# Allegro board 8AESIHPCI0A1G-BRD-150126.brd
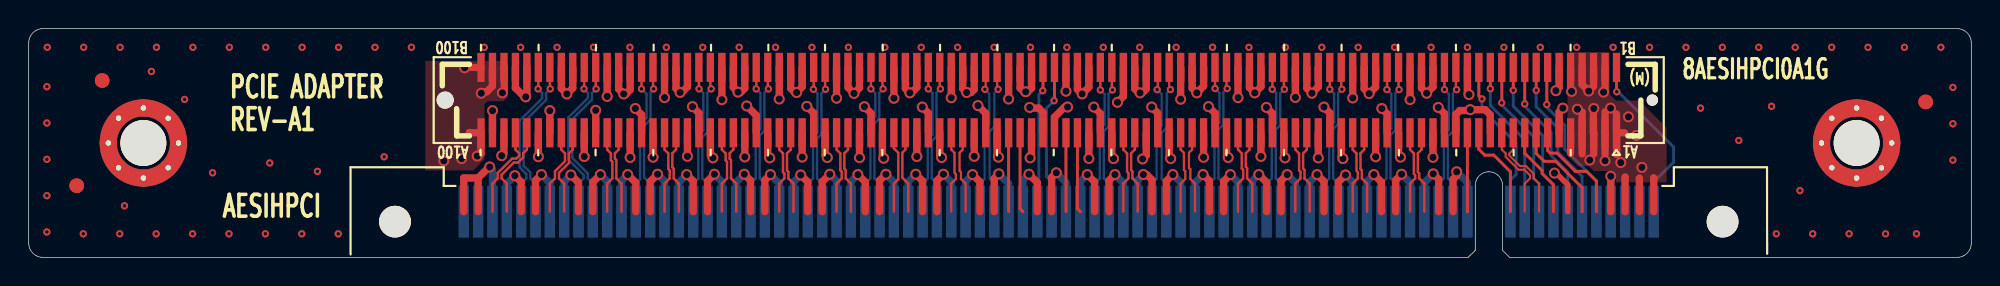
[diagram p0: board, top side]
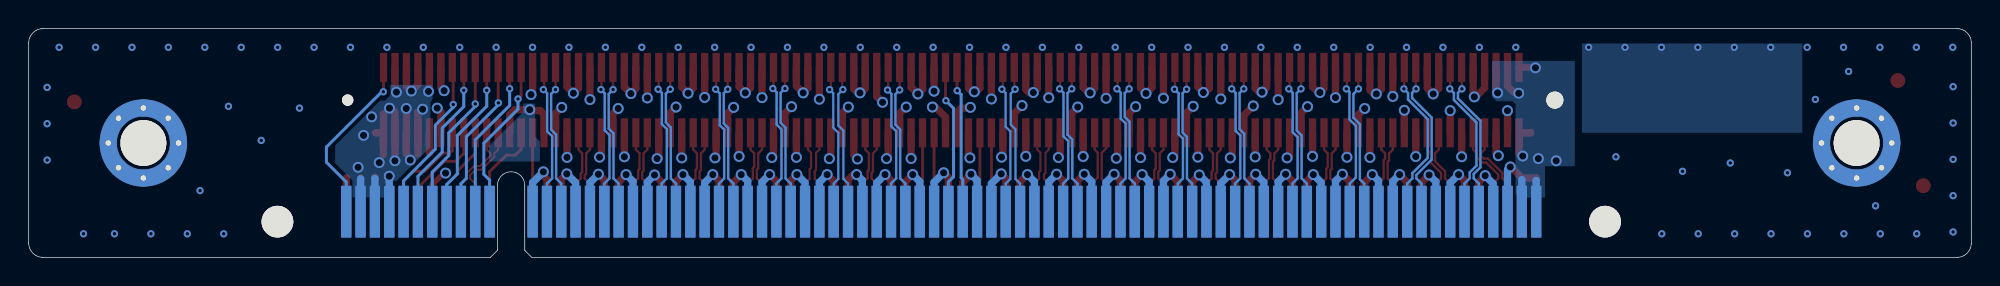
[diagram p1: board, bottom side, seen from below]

Outline 135.5 x 16 mm; copper layers: TOP, L2_GND, L3_GND, BOTTOM. Coordinates in mm from the lower left corner of the outline.

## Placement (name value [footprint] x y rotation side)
A1  3.5mm_8via  [A126_FG]  8 8 0 top
A2  3.5mm_8via  [A126_FG]  127.5 8 0 top
B1  Optics  [2B]  5.13 12.37 0 top
B2  Optics  [2B]  132.32 10.87 0 top
B3  Optics  [2B]  3.35 5.01 0 top
NOREF  -  []  13.9 11.11 0 top
NOREF#2  -  []  11.94 14.05 180 top
NOREF#3  -  []  140.41 20.29 0 top
NOREF#4  -  []  115.22 12.44 0 top
NOREF#5  ***  []  132.08 5.94 270 top
NOREF#6  -  []  0 0 0 top
P1  61083-202402LF  [C_5179029_0]  71.15 11 180 top
P2  2EG28217-D5D6-JF  [PCISR_E_X16_A]  118.15 2.5 180 bottom

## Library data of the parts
A1 A2 = SCREW HOLE_6: Tolerance: ***; User Part Number: ***; room: SCREW
B1-B3 = Optics_solder: Tolerance: ***; User Part Number: ***
P1 = HEADER_2X100B: Tolerance: ***; User Part Number: ***
P2 = 2134415-2_1: Tolerance: ***; User Part Number: ***

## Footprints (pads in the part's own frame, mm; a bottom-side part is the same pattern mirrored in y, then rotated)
2B
  round 1.016 smd: 1(0,0) 2(0,0)
A126_FG
  round 3.2 hole 3.2 unplated: (0,0)
  round 1.194 hole 0.381: 2(1.732,1.732) 3(-1.732,1.732) 4(-1.732,-1.732) 5(1.732,-1.732) 6(0,2.451) 7(0,-2.451) 8(-2.451,0) 9(2.451,0)
C_5179029_0
  round 0.787 hole 0.787 unplated: (-42.1,0)
  round 1.194 hole 1.194 unplated: (42.1,0)
  rect 0.508x2.032 smd: A1(-39.6,2.286) A2(-38.8,2.286) A3(-38,2.286) A4(-37.2,2.286) A5(-36.4,2.286) A6(-35.6,2.286) A7(-34.8,2.286) A8(-34,2.286) A9(-33.2,2.286) A10(-32.4,2.286) A11(-31.6,2.286) A12(-30.8,2.286) A13(-30,2.286) A14(-29.2,2.286) A15(-28.4,2.286) A16(-27.6,2.286) A17(-26.8,2.286) A18(-26,2.286) A19(-25.2,2.286) A20(-24.4,2.286) A21(-23.6,2.286) A22(-22.8,2.286) A23(-22,2.286) A24(-21.2,2.286) A25(-20.4,2.286) A26(-19.6,2.286) A27(-18.8,2.286) A28(-18,2.286) A29(-17.2,2.286) A30(-16.4,2.286) A31(-15.6,2.286) A32(-14.8,2.286) A33(-14,2.286) A34(-13.2,2.286) A35(-12.4,2.286) A36(-11.6,2.286) A37(-10.8,2.286) A38(-10,2.286) A39(-9.2,2.286) A40(-8.4,2.286) A41(-7.6,2.286) A42(-6.8,2.286) A43(-6,2.286) A44(-5.2,2.286) A45(-4.4,2.286) A46(-3.6,2.286) A47(-2.8,2.286) A48(-2,2.286) A49(-1.2,2.286) A50(-0.4,2.286) A51(0.4,2.286) A52(1.2,2.286) A53(2,2.286) A54(2.8,2.286) A55(3.6,2.286) A56(4.4,2.286) A57(5.2,2.286) A58(6,2.286) A59(6.8,2.286) A60(7.6,2.286) A61(8.4,2.286) A62(9.2,2.286) A63(10,2.286) A64(10.8,2.286) A65(11.6,2.286) A66(12.4,2.286) A67(13.2,2.286) A68(14,2.286) A69(14.8,2.286) A70(15.6,2.286) A71(16.4,2.286) A72(17.2,2.286) A73(18,2.286) A74(18.8,2.286) A75(19.6,2.286) A76(20.4,2.286) A77(21.2,2.286) A78(22,2.286) A79(22.8,2.286) A80(23.6,2.286) A81(24.4,2.286) A82(25.2,2.286) A83(26,2.286) A84(26.8,2.286) A85(27.6,2.286) A86(28.4,2.286) A87(29.2,2.286) A88(30,2.286) A89(30.8,2.286) A90(31.6,2.286) A91(32.4,2.286) A92(33.2,2.286) A93(34,2.286) A94(34.8,2.286) A95(35.6,2.286) A96(36.4,2.286) A97(37.2,2.286) A98(38,2.286) A99(38.8,2.286) A100(39.6,2.286) B1(-39.6,-2.286) B2(-38.8,-2.286) B3(-38,-2.286) B4(-37.2,-2.286) B5(-36.4,-2.286) B6(-35.6,-2.286) B7(-34.8,-2.286) B8(-34,-2.286) B9(-33.2,-2.286) B10(-32.4,-2.286) B11(-31.6,-2.286) B12(-30.8,-2.286) B13(-30,-2.286) B14(-29.2,-2.286) B15(-28.4,-2.286) B16(-27.6,-2.286) B17(-26.8,-2.286) B18(-26,-2.286) B19(-25.2,-2.286) B20(-24.4,-2.286) B21(-23.6,-2.286) B22(-22.8,-2.286) B23(-22,-2.286) B24(-21.2,-2.286) B25(-20.4,-2.286) B26(-19.6,-2.286) B27(-18.8,-2.286) B28(-18,-2.286) B29(-17.2,-2.286) B30(-16.4,-2.286) B31(-15.6,-2.286) B32(-14.8,-2.286) B33(-14,-2.286) B34(-13.2,-2.286) B35(-12.4,-2.286) B36(-11.6,-2.286) B37(-10.8,-2.286) B38(-10,-2.286) B39(-9.2,-2.286) B40(-8.4,-2.286) B41(-7.6,-2.286) B42(-6.8,-2.286) B43(-6,-2.286) B44(-5.2,-2.286) B45(-4.4,-2.286) B46(-3.6,-2.286) B47(-2.8,-2.286) B48(-2,-2.286) B49(-1.2,-2.286) B50(-0.4,-2.286) B51(0.4,-2.286) B52(1.2,-2.286) B53(2,-2.286) B54(2.8,-2.286) B55(3.6,-2.286) B56(4.4,-2.286) B57(5.2,-2.286) B58(6,-2.286) B59(6.8,-2.286) B60(7.6,-2.286) B61(8.4,-2.286) B62(9.2,-2.286) B63(10,-2.286) B64(10.8,-2.286) B65(11.6,-2.286) B66(12.4,-2.286) B67(13.2,-2.286) B68(14,-2.286) B69(14.8,-2.286) B70(15.6,-2.286) B71(16.4,-2.286) B72(17.2,-2.286) B73(18,-2.286) B74(18.8,-2.286) B75(19.6,-2.286) B76(20.4,-2.286) B77(21.2,-2.286) B78(22,-2.286) B79(22.8,-2.286) B80(23.6,-2.286) B81(24.4,-2.286) B82(25.2,-2.286) B83(26,-2.286) B84(26.8,-2.286) B85(27.6,-2.286) B86(28.4,-2.286) B87(29.2,-2.286) B88(30,-2.286) B89(30.8,-2.286) B90(31.6,-2.286) B91(32.4,-2.286) B92(33.2,-2.286) B93(34,-2.286) B94(34.8,-2.286) B95(35.6,-2.286) B96(36.4,-2.286) B97(37.2,-2.286) B98(38,-2.286) B99(38.8,-2.286) B100(39.6,-2.286)
PCISR_E_X16_A
  round 2.21 hole 2.21 unplated: (0,0) (92.6,0)
  rect 0.711x3.607 smd: A1(4.8,0.7) A2(5.8,0.7) A3(6.8,0.7) A4(7.8,0.7) A5(8.8,0.7) A6(9.8,0.7) A7(10.8,0.7) A8(11.8,0.7) A9(12.8,0.7) A10(13.8,0.7) A11(14.8,0.7) A12(17.8,0.7) A13(18.8,0.7) A14(19.8,0.7) A15(20.8,0.7) A16(21.8,0.7) A17(22.8,0.7) A18(23.8,0.7) A19(24.8,0.7) A20(25.8,0.7) A21(26.8,0.7) A22(27.8,0.7) A23(28.8,0.7) A24(29.8,0.7) A25(30.8,0.7) A26(31.8,0.7) A27(32.8,0.7) A28(33.8,0.7) A29(34.8,0.7) A30(35.8,0.7) A31(36.8,0.7) A32(37.8,0.7) A33(38.8,0.7) A34(39.8,0.7) A35(40.8,0.7) A36(41.8,0.7) A37(42.8,0.7) A38(43.8,0.7) A39(44.8,0.7) A40(45.8,0.7) A41(46.8,0.7) A42(47.8,0.7) A43(48.8,0.7) A44(49.8,0.7) A45(50.8,0.7) A46(51.8,0.7) A47(52.8,0.7) A48(53.8,0.7) A49(54.8,0.7) A50(55.8,0.7) A51(56.8,0.7) A52(57.8,0.7) A53(58.8,0.7) A54(59.8,0.7) A55(60.8,0.7) A56(61.8,0.7) A57(62.8,0.7) A58(63.8,0.7) A59(64.8,0.7) A60(65.8,0.7) A61(66.8,0.7) A62(67.8,0.7) A63(68.8,0.7) A64(69.8,0.7) A65(70.8,0.7) A66(71.8,0.7) A67(72.8,0.7) A68(73.8,0.7) A69(74.8,0.7) A70(75.8,0.7) A71(76.8,0.7) A72(77.8,0.7) A73(78.8,0.7) A74(79.8,0.7) A75(80.8,0.7) A76(81.8,0.7) A77(82.8,0.7) A78(83.8,0.7) A79(84.8,0.7) A80(85.8,0.7) A81(86.8,0.7) A82(87.8,0.7) B1(4.8,0.7) B2(5.8,0.7) B3(6.8,0.7) B4(7.8,0.7) B5(8.8,0.7) B6(9.8,0.7) B7(10.8,0.7) B8(11.8,0.7) B9(12.8,0.7) B10(13.8,0.7) B11(14.8,0.7) B12(17.8,0.7) B13(18.8,0.7) B14(19.8,0.7) B15(20.8,0.7) B16(21.8,0.7) B17(22.8,0.7) B18(23.8,0.7) B19(24.8,0.7) B20(25.8,0.7) B21(26.8,0.7) B22(27.8,0.7) B23(28.8,0.7) B24(29.8,0.7) B25(30.8,0.7) B26(31.8,0.7) B27(32.8,0.7) B28(33.8,0.7) B29(34.8,0.7) B30(35.8,0.7) B31(36.8,0.7) B32(37.8,0.7) B33(38.8,0.7) B34(39.8,0.7) B35(40.8,0.7) B36(41.8,0.7) B37(42.8,0.7) B38(43.8,0.7) B39(44.8,0.7) B40(45.8,0.7) B41(46.8,0.7) B42(47.8,0.7) B43(48.8,0.7) B44(49.8,0.7) B45(50.8,0.7) B46(51.8,0.7) B47(52.8,0.7) B48(53.8,0.7) B49(54.8,0.7) B50(55.8,0.7) B51(56.8,0.7) B52(57.8,0.7) B53(58.8,0.7) B54(59.8,0.7) B55(60.8,0.7) B56(61.8,0.7) B57(62.8,0.7) B58(63.8,0.7) B59(64.8,0.7) B60(65.8,0.7) B61(66.8,0.7) B62(67.8,0.7) B63(68.8,0.7) B64(69.8,0.7) B65(70.8,0.7) B66(71.8,0.7) B67(72.8,0.7) B68(73.8,0.7) B69(74.8,0.7) B70(75.8,0.7) B71(76.8,0.7) B72(77.8,0.7) B73(78.8,0.7) B74(79.8,0.7) B75(80.8,0.7) B76(81.8,0.7) B77(82.8,0.7) B78(83.8,0.7) B79(84.8,0.7) B80(85.8,0.7) B81(86.8,0.7) B82(87.8,0.7)

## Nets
12V_1: P1.A1(A1_P12V) P1.A2(A2_P12V) P1.A3(A3_P12V) P1.A4(A4_P12V) P1.A5(A5_P12V) P1.B2(B2_P12V) P1.B3(B3_P12V) P1.B4(B4_P12V) P1.B5(B5_P12V) P2.A2(P12V#A2) P2.A3(P12V#A3) P2.B1(P12V#B1) P2.B2(P12V#B2) P2.B3(P12V#B3)
12V_2: P1.A100(A100_P12V) P1.B98(B98_P12V) P1.B99(B99_P12V) P1.B100(B100_P12V) P2.A81(P12V#A81) P2.A82(P12V#A82)
GND: A1.2 A1.3 A1.4 A1.5 A1.6 A1.7 A1.8 A1.9 A2.2 A2.3 A2.4 A2.5 A2.6 A2.7 A2.8 A2.9 P1.A6(A6_GND) P1.A12(A12_USB_N) P1.A15(A15_GND) P1.A16(A16_GND) P1.A17(A17_GND) P1.A20(A20_GND) P1.A21(A21_GND) P1.A22(A22_GND) P1.A25(A25_GND) P1.A26(A26_GND) P1.A27(A27_GND) P1.A30(A30_GND) P1.A31(A31_GND) P1.A32(A32_GND) P1.A35(A35_GND) P1.A36(A36_GND) P1.A37(A37_GND) P1.A40(A40_GND) P1.A41(A41_GND) P1.A42(A42_GND) P1.A45(A45_GND) P1.A46(A46_GND) P1.A47(A47_GND) P1.A50(A50_GND) P1.A51(A51_GND) P1.A52(A52_GND) P1.A55(A55_GND) P1.A56(A56_GND) P1.A57(A57_GND) P1.A60(A60_GND) P1.A61(A61_GND) P1.A62(A62_GND) P1.A65(A65_GND) P1.A66(A66_GND) P1.A67(A67_GND) P1.A70(A70_GND) P1.A71(A71_GND) P1.A72(A72_GND) P1.A75(A75_GND) P1.A76(A76_GND) P1.A77(A77_GND) P1.A80(A80_GND) P1.A81(A81_GND) P1.A82(A82_GND) P1.A85(A85_GND) P1.A86(A86_GND) P1.A87(A87_GND) P1.A90(A90_GND) P1.A91(A91_GND) P1.A94(A94_GND) P1.A95(A95_GND) P1.A98(A98_GND) P1.A99(A99_GND) P1.B6(B6_GND) P1.B14(B14_GND) P1.B17(B17_GND) P1.B18(B18_GND) P1.B19(B19_GND) P1.B22(B22_GND) P1.B23(B23_GND) P1.B24(B24_GND) P1.B27(B27_GND) P1.B28(B28_GND) P1.B29(B29_GND) P1.B32(B32_GND) P1.B33(B33_GND) P1.B34(B34_GND) P1.B37(B37_GND) P1.B38(B38_GND) P1.B39(B39_GND) P1.B42(B42_GND) P1.B43(B43_GND) P1.B44(B44_GND) P1.B47(B47_GND) P1.B48(B48_GND) P1.B49(B49_GND) P1.B52(B52_GND) P1.B53(B53_GND) P1.B54(B54_GND) P1.B57(B57_GND) P1.B58(B58_GND) P1.B59(B59_GND) P1.B62(B62_GND) P1.B63(B63_GND) P1.B64(B64_GND) P1.B67(B67_GND) P1.B68(B68_GND) P1.B69(B69_GND) P1.B72(B72_GND) P1.B73(B73_GND) P1.B74(B74_GND) P1.B77(B77_GND) P1.B78(B78_GND) P1.B79(B79_GND) P1.B82(B82_GND) P1.B83(B83_GND) P1.B84(B84_GND) P1.B87(B87_GND) P1.B88(B88_GND) P1.B89(B89_GND) P1.B92(B92_GND) P1.B93(B93_GND) P1.B96(B96_GND) P1.B97(B97_GND) P2.A4(GND#A4) P2.A12(GND#A12) P2.A15(GND#A15) P2.A16(GND#A16) P2.A19(GND#A19) P2.A20(GND#A20) P2.A23(GND#A23) P2.A24(GND#A24) P2.A27(GND#A27) P2.A28(GND#A28) P2.A31(GND#A31) P2.A32(GND#A32) P2.A35(GND#A35) P2.A36(GND#A36) P2.A39(GND#A39) P2.A40(GND#A40) P2.A43(GND#A43) P2.A44(GND#A44) P2.A47(GND#A47) P2.A48(GND#A48) P2.A51(GND#A51) P2.A52(GND#A52) P2.A55(GND#A55) P2.A56(GND#A56) P2.A59(GND#A59) P2.A60(GND#A60) P2.A63(GND#A63) P2.A64(GND#A64) P2.A67(GND#A67) P2.A68(GND#A68) P2.A71(GND#A71) P2.A72(GND#A72) P2.A75(GND#A75) P2.A76(GND#A76) P2.A79(GND#A79) P2.A80(GND#A80) P2.B4(GND#B4) P2.B7(GND#B7) P2.B13(GND#B13) P2.B14(GND#B14) P2.B17(GND#B17) P2.B18(GND#B18) P2.B21(GND#B21) P2.B22(GND#B22) P2.B25(GND#B25) P2.B26(GND#B26) P2.B29(GND#B29) P2.B30(GND#B30) P2.B33(GND#B33) P2.B34(GND#B34) P2.B37(GND#B37) P2.B38(GND#B38) P2.B41(GND#B41) P2.B42(GND#B42) P2.B45(GND#B45) P2.B46(GND#B46) P2.B49(GND#B49) P2.B50(GND#B50) P2.B53(GND#B53) P2.B54(GND#B54) P2.B57(GND#B57) P2.B58(GND#B58) P2.B61(GND#B61) P2.B62(GND#B62) P2.B65(GND#B65) P2.B66(GND#B66) P2.B69(GND#B69) P2.B70(GND#B70) P2.B73(GND#B73) P2.B74(GND#B74) P2.B77(GND#B77) P2.B78(GND#B78) P2.B81(GND#B81) P2.B82(GND#B82)
COM_RX: P1.B10(B10_COM_RX) P2.A8(COM_RX)
COM_TX: P1.B9(B9_COM_TX) P2.A7(COM_TX)
GE0_RX_N: P1.B56(B56_GE0_RX_N) P2.A46(GE0_RX_N)
GE0_RX_P: P1.B55(B55_GE0_RX_P) P2.A45(GE0_RX_P)
GE0_TX_N: P1.A59(A59_GE0_TX_N) P2.B48(GE0_TX_N)
GE0_TX_P: P1.A58(A58_GE0_TX_P) P2.B47(GE0_TX_P)
I2C_ALERT_N: P1.A14(A14_I2C_ALERT) P2.B12(I2C_ALERT#)
I2C_DATA: P1.A8(A8_I2C_DATA) P2.B6(I2C_DATA)
I2C_SCL: P1.A7(A7_I2C_SCL) P2.B5(I2C_SCL)
NIC_SMBUS_ALERT: P1.B51(B51_NIC_SMBUS_ALERT#) P2.A42(NIC_SMBUS_ALERT#)
NIC_SMBUS_SCL: P1.A53(A53_NIC_SMBUS_SCL) P2.B43(NIC_SMBUS_SCL)
NIC_SMBUS_SDA: P1.A54(A54_NIC_SMBUS_SDA) P2.B44(NIC_SMBUS_SDA)
PCIE0_REFCLK_N: P1.B16(B16_PCIE0_REFCLK_N) P2.A14(PCIE0_REFCLK_N)
PCIE0_REFCLK_P: P1.B15(B15_PCIE0_REFCLK_P) P2.A13(PCIE0_REFCLK_P)
PCIE0_RST_N: P1.B13(B13_PCIE0_RESET#) P2.A11(PCIE0_RESET#)
PCIE0_RX0_N: P1.B21(B21_PCIE0_RX0_N) P2.A18(PCIE0_RX0_N)
PCIE0_RX0_P: P1.B20(B20_PCIE0_RX0_P) P2.A17(PCIE0_RX0_P)
PCIE0_RX1_N: P1.B26(B26_PCIE0_RX1_N) P2.A22(PCIE0_RX1_N)
PCIE0_RX1_P: P1.B25(B25_PCIE0_RX1_P) P2.A21(PCIE0_RX1_P)
PCIE0_RX2_N: P1.B31(B31_PCIE0_RX2_N) P2.A26(PCIE0_RX2_N)
PCIE0_RX2_P: P1.B30(B30_PCIE0_RX2_P) P2.A25(PCIE0_RX2_P)
PCIE0_RX3_N: P1.B36(B36_PCIE0_RX3_N) P2.A30(PCIE0_RX3_N)
PCIE0_RX3_P: P1.B35(B35_PCIE0_RX3_P) P2.A29(PCIE0_RX3_P)
PCIE0_RX4_N: P1.B61(B61_PCIE0_RX4_N) P2.A50(PCIE0_RX4_N)
PCIE0_RX4_P: P1.B60(B60_PCIE0_RX4_P) P2.A49(PCIE0_RX4_P)
PCIE0_RX5_N: P1.B66(B66_PCIE0_RX5_N) P2.A54(PCIE0_RX5_N)
PCIE0_RX5_P: P1.B65(B65_PCIE0_RX5_P) P2.A53(PCIE0_RX5_P)
PCIE0_RX6_N: P1.B71(B71_PCIE0_RX6_N) P2.A58(PCIE0_RX6_N)
PCIE0_RX6_P: P1.B70(B70_PCIE0_RX6_P) P2.A57(PCIE0_RX6_P)
PCIE0_RX7_N: P1.B76(B76_PCIE0_RX7_N) P2.A62(PCIE0_RX7_N)
PCIE0_RX7_P: P1.B75(B75_PCIE0_RX7_P) P2.A61(PCIE0_RX7_P)
PCIE0_TX0_N: P1.A19(A19_PCIE0_TX0_N) P2.B16(PCIE0_TX0_N)
PCIE0_TX0_P: P1.A18(A18_PCIE0_TX0_P) P2.B15(PCIE0_TX0_P)
PCIE0_TX1_N: P1.A24(A24_PCIE0_TX1_N) P2.B20(PCIE0_TX1_N)
PCIE0_TX1_P: P1.A23(A23_PCIE0_TX1_P) P2.B19(PCIE0_TX1_P)
PCIE0_TX2_N: P1.A29(A29_PCIE0_TX2_N) P2.B24(PCIE0_TX2_N)
PCIE0_TX2_P: P1.A28(A28_PCIE0_TX2_P) P2.B23(PCIE0_TX2_P)
PCIE0_TX3_N: P1.A34(A34_PCIE0_TX3_N) P2.B28(PCIE0_TX3_N)
PCIE0_TX3_P: P1.A33(A33_PCIE0_TX3_P) P2.B27(PCIE0_TX3_P)
PCIE0_TX4_N: P1.A64(A64_PCIE0_TX4_N) P2.B52(PCIE0_TX4_N)
PCIE0_TX4_P: P1.A63(A63_PCIE0_TX4_P) P2.B51(PCIE0_TX4_P)
PCIE0_TX5_N: P1.A69(A69_PCIE0_TX5_N) P2.B56(PCIE0_TX5_N)
PCIE0_TX5_P: P1.A68(A68_PCIE0_TX5_P) P2.B55(PCIE0_TX5_P)
PCIE0_TX6_N: P1.A74(A74_PCIE0_TX6_N) P2.B60(PCIE0_TX6_N)
PCIE0_TX6_P: P1.A73(A73_PCIE0_TX6_P) P2.B59(PCIE0_TX6_P)
PCIE0_TX7_N: P1.A79(A79_PCIE0_TX7_N) P2.B64(PCIE0_TX7_N)
PCIE0_TX7_P: P1.A78(A78_PCIE0_TX7_P) P2.B63(PCIE0_TX7_P)
PCIE1_REFCLK_N: P1.A44(A44_PCIE1_REFCLK_N) P2.B36(PCIE1_REFCLK_N)
PCIE1_REFCLK_P: P1.A43(A43_PCIE1_REFCLK_P) P2.B35(PCIE1_REFCLK_P)
PCIE1_RST_N: P1.A48(A48_PCIE1_RESET#) P2.B39(PCIE1_RESET#)
PCIE1_RX0_N: P1.B81(B81_PCIE1_RX0_N) P2.A66(PCIE1_RX0_N)
PCIE1_RX0_P: P1.B80(B80_PCIE1_RX0_P) P2.A65(PCIE1_RX0_P)
PCIE1_RX1_N: P1.B86(B86_PCIE1_RX1_N) P2.A70(PCIE1_RX1_N)
PCIE1_RX1_P: P1.B85(B85_PCIE1_RX1_P) P2.A69(PCIE1_RX1_P)
PCIE1_RX2_N: P1.B91(B91_PCIE1_RX2_N) P2.A74(PCIE1_RX2_N)
PCIE1_RX2_P: P1.B90(B90_PCIE1_RX2_P) P2.A73(PCIE1_RX2_P)
PCIE1_RX3_N: P1.B95(B95_PCIE1_RX3_N) P2.A78(PCIE1_RX3_N)
PCIE1_RX3_P: P1.B94(B94_PCIE1_RX3_P) P2.A77(PCIE1_RX3_P)
PCIE1_TX0_N: P1.A84(A84_PCIE1_TX0_N) P2.B68(PCIE1_TX0_N)
PCIE1_TX0_P: P1.A83(A83_PCIE1_TX0_P) P2.B67(PCIE1_TX0_P)
PCIE1_TX1_N: P1.A89(A89_PCIE1_TX1_N) P2.B72(PCIE1_TX1_N)
PCIE1_TX1_P: P1.A88(A88_PCIE1_TX1_P) P2.B71(PCIE1_TX1_P)
PCIE1_TX2_N: P1.A93(A93_PCIE1_TX2_N) P2.B76(PCIE1_TX2_N)
PCIE1_TX2_P: P1.A92(A92_PCIE1_TX2_P) P2.B75(PCIE1_TX2_P)
PCIE1_TX3_N: P1.A97(A97_PCIE1_TX3_N) P2.B80(PCIE1_TX3_N)
PCIE1_TX3_P: P1.A96(A96_PCIE1_TX3_P) P2.B79(PCIE1_TX3_P)
PCIE2_REFCLK_N: P1.B46(B46_PCIE2_REFCLK_N) P2.A38(PCIE2_REFCLK_N)
PCIE2_REFCLK_P: P1.B45(B45_PCIE2_REFCLK_P) P2.A37(PCIE2_REFCLK_P)
PCIE2_RST_N: P1.A49(A49_PCIE2_RESET#) P2.B40(PCIE2_RESET#)
PRSNT_N: P1.B1(B1_PRSNT#) P2.A1(PRSNT#)
PWR_BTN_N: P1.A9(A9_GND) P2.B8(PWR_BTN#)
RFU: P1.B50(B50_RFU) P2.A41(RFU)
SATA0_RX_N: P1.B41(B41_SATA0_RX_N) P2.A34(SATA0_RX_N)
SATA0_RX_P: P1.B40(B40_SATA0_RX_P) P2.A33(SATA0_RX_P)
SATA0_TX_N: P1.A39(A39_SATA0_TX_N) P2.B32(SATA0_TX_N)
SATA0_TX_P: P1.A38(A38_SATA0_TX_P) P2.B31(SATA0_TX_P)
SVR_ID0: P1.B7(B7_SVR_ID0/GPIO0) P2.A5(SVR_ID0/GPIO0)
SVR_ID1: P1.B8(B8_SVR_ID1/GPIO1) P2.A6(SVR_ID1/GPIO1)
SVR_ID2: P1.B11(B11_SVR_ID2/GPIO2) P2.A9(SVR_ID2/GPIO2)
SVR_ID3: P1.B12(B12_SVR_ID3/GPIO3) P2.A10(SVR_ID3/GPIO3)
SYS_RST_N: P1.A13(A13_SYS_RESET#) P2.B11(SYS_RESET#)
USB_DN: P1.A11(A11_USB_P) P2.B10(USB_N)
USB_DP: P1.A10(A10_PWR_BTN#) P2.B9(USB_P)

Pads without a net: B1 1 2; B2 1 2; B3 1 2

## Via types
v1: diameter 0.762, hole 0.508, TOP to BOTTOM, 141 vias
v2: diameter 0.508, hole 0.254, TOP to BOTTOM, 126 vias

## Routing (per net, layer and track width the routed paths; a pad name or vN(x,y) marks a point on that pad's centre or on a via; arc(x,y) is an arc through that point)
12V_1: length 32.6
  TOP w0.508: P2.A2 112.35,5.53 112.34,5.54 ; 109.95,7.21 109.95,8.71 ; 109.95,8.71 109.95,10.19 ; 109.95,8.71 P1.A2 ; P2.A3 111.35,5.61 111.35,5.61 ; 108.35,7.24 108.35,8.71 P1.A4 108.35,10.16 108.35,10.16 ; P1.B2 109.95,11.66 v1(109.85,11.56) ; 111.31,8.71 110.77,8.71 ; 110.77,8.71 P1.A1 110.75,10.04 ; 110.77,8.71 110.77,7.19 ; 109.16,7.24 109.16,8.71 P1.A3 109.14,8.71 109.14,10.21 ; P1.B4 108.35,12.09 v1(108.81,11.63) 109.15,11.97 P1.B3 ; v1(107.62,11.61) 107.55,11.67 P1.B5 ; P1.A5 107.55,7.28 ; 113.33,5.56 113.35,5.55 P2.B1
  BOTTOM w0.508: P2.A2 112.35,5.48 112.34,5.49 ; 111.35,5.51 111.35,5.51 P2.A3
  vias: v1(108.02,10.36) v1(108.89,6.81) v1(109.16,10.41) v1(109.95,6.76) v1(110.33,10.44) v1(111.05,6.63) v1(111.58,9.83) v1(112.14,8.53) v1(112.52,6.3)
12V_2: length 12.3
  TOP w0.508: v1(30.41,13.26) 30.43,13.29 P1.B100 ; v1(31.29,7.09) 31.39,7.09 31.55,7.25 P1.A100 30.75,8.71 30.73,8.74 ; P1.B98 33.17,13.27 33.17,11.63 v1(33.04,11.51) ; v1(31.57,11.48) 31.67,11.58 31.95,11.58 32.35,11.98 P1.B99
  BOTTOM w0.508: P2.A81 31.35,5.43 31.34,5.44 ; P2.A82 30.35,5.38 30.35,5.38
  vias: v1(28.96,6.76) v1(30.2,6.91)
GND: length 412.2
  TOP w0.381: v1(106.42,5.9) 106.54,5.9 107.35,5.09 P2.B7
  TOP w0.508: 31.35,5.56 32.12,6.32 v1(32.16,6.32) ; 31.35,5.56 P2.B81 ; 31.35,5.56 30.35,5.56 P2.B82 ; P1.B78 49.15,11.88 v1(49.47,11.56) 49.68,11.56 49.95,11.83 P1.B77 ; P1.B52 69.95,11.84 69.69,11.58 v1(69.54,11.58) 69.41,11.58 69.15,11.85 P1.B53 ; P1.A27 v1(89.95,6.96) ; v1(55.88,5.82) 55.35,5.29 P2.B57 ; P1.A20 95.55,7.14 v1(95.68,7.01) ; P1.A50 71.55,9.81 72.26,10.52 v1(72.46,10.52) ; v1(67.67,5.84) 67.35,5.53 P2.B45 ; P1.B69 v1(56.35,11.13) ; v1(81.92,5.79) 82.35,5.36 P2.B30 ; P1.A56 66.75,10.08 v1(66.21,10.62) ; P2.B77 35.35,5.38 v1(35.76,5.79) ; P1.A67 v1(57.95,6.98) ; P1.B48 73.15,11.76 v1(73.48,11.43) 73.95,11.9 P1.B47 ; P1.B82 45.95,11.93 45.55,11.53 v1(45.44,11.53) 45.15,11.82 P1.B83 ; P2.B13 99.35,5.46 99.6,5.72 v1(99.6,5.99) ; v1(86.33,10.49) 86.75,10.07 P1.A31 ; P1.B73 53.15,11.82 53.44,11.53 v1(53.56,11.53) 53.95,11.92 P1.B72 ; P2.B74 38.35,5.24 v1(37.82,5.77) ; P1.A80 47.55,7.14 v1(47.73,6.96) ; P1.A51 70.75,10.14 70.45,10.44 69.87,10.44 v1(69.82,10.49) ; P1.A30 87.55,7.04 v1(87.63,6.96) ; v1(55.7,6.99) 55.55,7.14 P1.A70 ; P2.B22 90.35,5.31 v1(89.87,5.79) ; P1.B96 34.75,11.31 v1(34.67,11.23) 34.57,11.23 33.95,11.85 P1.B97 ; P1.A55 67.55,7.1 v1(67.64,7.01) ; P2.B37 75.35,5.37 v1(75.77,5.79) ; P2.B14 98.35,5.46 v1(97.97,5.84) ; P1.A61 62.75,10.09 v1(62.33,10.52) ; P1.A91 v1(38.75,7.06) ; P1.A6 106.75,10.18 v1(107.01,10.44) ; P1.B88 41.15,11.78 v1(41.5,11.43) 41.66,11.43 41.95,11.71 P1.B87 ; P1.B42 77.95,11.79 77.69,11.53 77.54,11.53 v1(77.52,11.51) 77.44,11.51 77.15,11.8 P1.B43 ; P2.B49 63.35,5.36 v1(63.8,5.82) ; v1(57.84,5.79) 58.35,5.28 P2.B54 ; v1(85.8,5.79) 86.35,5.24 P2.B26 ; P1.B32 85.95,11.94 v1(85.52,11.51) 85.15,11.87 P1.B33 ; P1.A17 v1(97.95,7) ; P1.B22 93.95,11.91 v1(93.49,11.46) 93.15,11.8 P1.B23 ; P1.A71 54.75,10.09 v1(54.28,10.57) ; v1(61.87,5.82) 62.35,5.34 P2.B50 ; v1(106.52,11.66) 106.75,11.89 P1.B6 ; P1.B89 v1(40.35,11.26) ; P1.B64 v1(60.35,11.13) ; P2.B46 66.35,5.28 v1(65.84,5.79) ; v1(87.78,5.79) 87.35,5.36 P2.B25 ; P2.B38 74.35,5.28 v1(73.84,5.79) ; v1(91.85,5.77) 91.35,5.27 P2.B21 ; v1(42.31,10.41) 42.75,9.98 P1.A86 ; P2.B18 94.35,5.27 v1(93.83,5.79) ; P1.B74 v1(52.35,11.08) ; v1(32.36,10.26) 32.35,10.26 P1.A99 ; P1.A81 46.75,10.09 v1(46.3,10.54) ; P2.B41 71.35,5.59 v1(71.68,5.92) ; P1.A37 v1(81.95,7) ; v1(98.32,10.49) 98.75,10.06 P1.A16 ; P2.B33 79.35,5.33 v1(79.81,5.79) ; P2.B53 59.35,5.37 v1(59.79,5.82) ; P1.B79 v1(48.35,11.03) ; v1(47.83,5.82) 47.35,5.34 P2.B65 ; P1.A32 v1(85.95,7.06) ; P1.B84 v1(44.35,11.18) ; v1(69.85,6.96) 69.85,7.14 69.95,7.24 P1.A52 ; P1.B49 v1(72.35,11.62) ; P1.B58 65.15,11.81 v1(65.43,11.53) 65.73,11.53 65.95,11.75 P1.B57 ; v1(91.67,6.91) 91.55,7.03 P1.A25 ; P1.A22 v1(93.95,7.04) ; v1(45.9,5.79) 46.35,5.34 P2.B66 ; P1.A26 90.75,10.11 v1(90.34,10.52) ; P1.B67 57.95,11.85 v1(57.56,11.47) 57.15,11.88 P1.B68 ; P2.B29 83.35,5.32 v1(83.82,5.79) ; v1(77.69,6.88) 77.95,7.14 P1.A42 ; P1.A82 v1(45.95,7.07) ; P1.A94 v1(36.35,10.26) ; P1.A57 v1(65.95,7.07) ; v1(78.33,10.52) 78.75,10.09 P1.A41 ; P1.A60 63.55,7.11 v1(63.68,6.99) ; P2.B70 42.35,5.22 v1(41.78,5.79) ; P1.B54 v1(68.35,11.08) ; P1.A76 50.75,9.93 v1(50.08,10.59) ; v1(49.91,5.82) 50.35,5.38 P2.B62 ; P1.B14 100.35,11.5 v1(100.46,11.39) ; v1(94.38,10.41) 94.75,10.05 P1.A21 ; v1(53.85,5.77) 54.35,5.26 P2.B58 ; P1.A98 33.15,7.27 v1(32.99,7.11) ; P1.A46 74.75,10.06 v1(74.29,10.52) ; P1.A47 v1(73.95,6.92) ; v1(79.65,6.91) 79.55,7.01 P1.A40 ; P1.A75 51.55,7.1 v1(51.69,6.96) ; P1.B93 37.15,11.82 v1(37.54,11.43) 37.95,11.84 P1.B92 ; P1.B37 81.95,11.98 v1(81.48,11.51) 81.15,11.84 P1.B38 ; P1.A90 v1(39.55,10.29) ; P2.B42 70.35,5.24 v1(69.77,5.82) ; v1(33.91,5.71) 34.35,5.27 P2.B78 ; P1.B19 v1(96.35,11.04) ; P1.B29 v1(88.35,11.19) ; P1.B17 97.95,11.92 v1(97.51,11.48) 97.15,11.84 P1.B18 ; P1.B24 v1(92.35,11.15) ; P2.B69 43.35,5.3 v1(43.87,5.82) ; P1.A77 v1(49.95,7.03) ; P1.A12 101.95,9.97 101.59,10.33 v1(100.55,10.33) 100.49,10.27 99.83,10.27 99.55,10 P1.A15 ; P1.A66 58.75,10.08 v1(58.29,10.54) ; P2.A4 v1(110.35,5.68) ; P1.A87 v1(41.95,6.99) ; v1(82.29,10.54) 82.75,10.08 P1.A36 ; v1(75.67,6.91) 75.55,7.03 P1.A45 ; P1.B28 89.15,11.84 v1(89.51,11.48) 89.95,11.93 P1.B27 ; P2.B17 95.35,5.41 v1(95.76,5.82) ; v1(39.88,5.79) 39.35,5.26 P2.B73 ; v1(83.67,6.99) 83.55,7.1 P1.A35 ; v1(75.94,10.85) 76.35,11.25 P1.B44 ; P1.B39 v1(80.35,11.06) ; P1.A85 v1(43.55,7) ; P1.B63 61.15,11.82 v1(61.46,11.51) 61.57,11.51 61.95,11.89 P1.B62 ; P1.B59 v1(64.35,11.17) ; v1(77.75,5.79) 77.98,5.79 78.35,5.42 P2.B34 ; P1.A65 59.55,7.02 v1(59.64,6.93) ; v1(51.74,5.79) 51.35,5.4 P2.B61 ; P1.A95 v1(35.55,7.04) ; P1.B34 v1(84.35,11.17) ; P1.A62 v1(61.95,7.06) ; P1.A72 v1(53.95,7.01)
  BOTTOM w0.508: P2.A32 80.35,5.25 v1(79.81,5.79) ; v1(47.83,5.82) 48.35,5.29 P2.A64 ; v1(53.85,5.77) 53.35,5.27 P2.A59 ; P2.A52 60.35,5.26 v1(59.79,5.82) ; v1(75.77,5.79) 76.35,5.21 P2.A36 ; P2.A56 56.35,5.35 v1(55.88,5.82) ; v1(73.84,5.79) 73.35,5.3 P2.A39 ; v1(35.76,5.79) 36.35,5.2 P2.A76 ; P2.A75 37.35,5.3 v1(37.82,5.77) ; P2.A35 77.35,5.39 v1(77.75,5.79) ; v1(67.67,5.84) 68.35,5.16 P2.A44 ; P2.A23 89.35,5.28 v1(89.87,5.79) ; P2.A31 81.35,5.23 v1(81.92,5.79) ; P2.A55 57.35,5.31 v1(57.84,5.79) ; P2.A4 v1(110.35,5.68) ; P2.A19 93.35,5.31 v1(93.83,5.79) ; v1(41.78,5.79) 41.35,5.36 P2.A71 ; P2.A16 96.35,5.22 v1(95.76,5.82) ; P2.A20 92.35,5.26 v1(91.85,5.77) ; v1(97.97,5.84) 97.35,5.22 P2.A15 ; v1(85.8,5.79) 85.35,5.34 P2.A27 ; v1(32.16,6.32) 32.35,6.13 P2.A80 ; P2.A40 72.35,5.25 v1(71.68,5.92) ; v1(65.84,5.79) 65.35,5.3 P2.A47 ; P2.A79 33.35,5.16 v1(33.91,5.71) ; v1(69.77,5.82) 69.35,5.39 P2.A43 ; P2.A68 44.35,5.33 v1(43.87,5.82) ; v1(39.88,5.79) 40.35,5.32 P2.A72 ; v1(83.82,5.79) 84.35,5.26 P2.A28 ; P2.A24 88.35,5.22 v1(87.78,5.79) ; v1(49.91,5.82) 49.35,5.26 P2.A63 ; v1(45.9,5.79) 45.35,5.24 P2.A67 ; P2.A12 100.35,5.23 99.69,5.9 99.69,5.9 v1(99.6,5.99) ; P2.A48 64.35,5.27 v1(63.8,5.82) ; v1(51.74,5.79) 52.35,5.18 P2.A60 ; v1(61.87,5.82) 61.35,5.29 P2.A51
  vias: v2(1.29,14.69) v2(1.27,11.94) v2(1.27,9.4) v2(1.27,6.86) v2(1.27,4.32) v2(1.27,1.78) v2(3.83,14.69) v2(3.81,1.65) v2(6.35,1.65) v2(6.37,14.69) v2(6.68,3.61) v2(8.56,13) v2(8.91,14.69) v2(8.89,1.65) v2(10.88,11.05) v2(11.43,1.65) v2(11.45,14.69) v2(12.83,5.92) v2(13.99,14.69) v2(13.97,1.65) v2(16.53,14.69) v2(16.51,1.65) v2(16.81,6.6) v2(19.07,14.69) v2(19.05,1.65) v2(20.14,6.02) v2(21.61,14.69) v2(21.59,1.65) v2(24.15,14.69) v2(24.79,7.04) v2(26.69,14.69) v2(31.77,14.69) v2(34.31,14.69) v2(36.85,14.69) v2(39.39,14.69) v2(41.93,14.69) v2(44.47,14.69) v2(47.01,14.69) v2(49.55,14.69) v2(52.09,14.69) v2(54.63,14.69) v2(57.17,14.69) v2(59.71,14.69) v2(62.25,14.69) v2(64.79,14.69) v2(67.33,14.69) v2(69.87,14.69) v2(72.41,14.69) v2(74.95,14.69) v2(77.49,14.69) v2(80.03,14.69) v2(82.57,14.69) v2(85.11,14.69) v2(87.65,14.69) v2(90.19,14.69) v2(92.73,14.69) v2(95.27,14.69) v2(97.81,14.69) v2(100.35,14.69) v2(102.89,14.69) v2(105.43,14.69) v2(107.97,14.69) v2(110.51,14.69) v2(113.05,14.69) v2(115.59,14.69) v2(116.61,10.44) v2(118.13,14.69) v2(119.28,8.18) v2(120.67,14.69) v2(121.56,10.57) v2(121.89,1.65) v2(123.21,14.69) v2(123.55,4.67) v2(124.43,1.65) v2(125.75,14.69) v2(126.97,1.65) v2(128.29,14.69) v2(129.51,1.65) v2(130.83,14.69) v2(131.67,1.65) v2(133.37,14.69) v2(134.21,11.89) v2(134.21,9.35) v2(134.21,6.81)
COM_RX: length 11.2
  TOP w0.203: P1.B10 v2(103.55,11.69)
  BOTTOM w0.203: v2(103.55,11.69) 103.55,10.57 105.6,8.52 105.6,5.83 106.35,5.09 P2.A8
COM_TX: length 11.3
  TOP w0.203: P1.B9 v2(104.35,10.73)
  BOTTOM w0.203: v2(104.35,10.73) 104.35,10.56 106.2,8.71 106.2,7.12 107.35,5.96 P2.A7
GE0_RX_N: length 10.5
  TOP w0.152: P1.B56 66.75,11.81 v2(66.7,11.76)
  BOTTOM w0.152: P2.A46 66.35,5.16 66.67,5.48 66.67,8.96 67,9.29 67,11.46 v2(66.7,11.76)
GE0_RX_P: length 10.5
  TOP w0.152: P1.B55 67.55,11.83 v2(67.62,11.76)
  BOTTOM w0.152: v2(67.62,11.76) 67.36,11.5 67.36,9.14 67.03,8.81 67.03,5.48 67.35,5.16 P2.A45
GE0_TX_N: length 5.8
  TOP w0.152: P2.B48 64.35,5.16 64.67,5.48 64.67,5.81 64.58,5.91 64.58,7.31 64.35,7.54 P1.A59
GE0_TX_P: length 5.8
  TOP w0.152: P2.B47 65.35,5.16 65.03,5.48 65.03,5.96 64.93,6.06 64.93,7.32 65.15,7.54 P1.A58
I2C_ALERT_N: length 5.5
  TOP w0.203: P1.A14 P2.B12
I2C_DATA: length 7.3
  TOP w0.203: P2.B6 108.36,3.21 108.36,4.87 106.51,6.72 105.7,6.72 105.15,7.27 P1.A8
I2C_SCL: length 7.7
  TOP w0.203: P2.B5 109.35,3.2 109.35,5.33 108.66,6.02 107.88,6.02 106.61,7.29 106.13,7.29 105.95,7.47 P1.A7
NIC_SMBUS_ALERT: length 10.3
  TOP w0.203: v2(70.73,11.66) 70.75,11.67 P1.B51
  BOTTOM w0.203: P2.A42 70.35,5.45 70.46,5.56 70.46,11.38 v2(70.73,11.66)
NIC_SMBUS_SCL: length 5.6
  TOP w0.203: P2.B43 69.15,3.4 P1.A53
NIC_SMBUS_SDA: length 5.5
  TOP w0.203: P1.A54 P2.B44
PCIE0_REFCLK_N: length 10.5
  TOP w0.165: P1.B16 98.75,11.74 v2(98.75,11.73)
  BOTTOM w0.165: v2(98.75,11.73) 99.06,11.43 99.06,8.93 98.71,8.58 98.71,5.53 98.35,5.17 P2.A14
PCIE0_REFCLK_P: length 10.5
  TOP w0.165: v2(99.6,11.73) 99.55,11.78 P1.B15
  BOTTOM w0.165: v2(99.6,11.73) 99.34,11.47 99.34,8.82 98.99,8.47 98.99,5.53 99.35,5.16 P2.A13
PCIE0_RST_N: length 11.3
  TOP w0.203: v2(101.37,11.08) 101.15,11.3 P1.B13
  BOTTOM w0.203: P2.A11 103.35,5.4 103.75,5.81 103.75,7.98 101.37,10.37 v2(101.37,11.08)
PCIE0_RX0_N: length 10.5
  TOP w0.165: P1.B21 94.75,11.75 v2(94.74,11.73)
  BOTTOM w0.165: P2.A18 94.35,5.17 94.71,5.53 94.71,8.67 94.89,8.85 95.04,9.01 95.04,11.43 v2(94.74,11.73)
PCIE0_RX0_P: length 10.5
  TOP w0.165: P1.B20 95.55,11.77 v2(95.58,11.73)
  BOTTOM w0.165: v2(95.58,11.73) 95.32,11.47 95.32,8.89 94.99,8.56 94.99,5.53 95.35,5.16 P2.A17
PCIE0_RX1_N: length 10.5
  TOP w0.165: P1.B26 v2(90.75,11.76)
  BOTTOM w0.165: v2(90.75,11.76) 91.06,11.45 91.06,9.44 90.71,9.09 90.71,5.53 90.35,5.17 P2.A22
PCIE0_RX1_P: length 10.5
  TOP w0.165: P1.B25 91.55,11.81 v2(91.6,11.76)
  BOTTOM w0.165: v2(91.6,11.76) 91.33,11.5 91.33,9.32 90.99,8.98 90.99,5.53 91.35,5.16 P2.A21
PCIE0_RX2_N: length 10.5
  TOP w0.165: P1.B31 86.75,11.77 v2(86.74,11.76)
  BOTTOM w0.165: v2(86.74,11.76) 87.02,11.48 87.02,9.36 86.83,9.18 86.71,9.06 86.71,5.53 86.35,5.17 P2.A26
PCIE0_RX2_P: length 10.5
  TOP w0.165: v2(87.58,11.76) 87.55,11.79 P1.B30
  BOTTOM w0.165: P2.A25 87.35,5.16 86.99,5.53 86.99,8.94 87.3,9.25 87.3,11.47 v2(87.58,11.76)
PCIE0_RX3_N: length 10.5
  TOP w0.165: P1.B36 82.75,11.81 v2(82.75,11.81)
  BOTTOM w0.165: v2(82.75,11.81) 83.05,11.51 83.05,9.41 82.71,9.07 82.71,5.53 82.35,5.17 P2.A30
PCIE0_RX3_P: length 10.5
  TOP w0.165: P1.B35 83.55,11.86 v2(83.6,11.81)
  BOTTOM w0.165: v2(83.6,11.81) 83.33,11.55 83.33,9.29 83.07,9.03 82.99,8.95 82.99,5.53 83.35,5.16 P2.A29
PCIE0_RX4_N: length 10.5
  TOP w0.165: P1.B61 62.75,11.79 v2(62.75,11.79)
  BOTTOM w0.165: P2.A50 62.35,5.16 62.71,5.53 62.71,8.25 63.04,8.58 63.04,11.49 v2(62.75,11.79)
PCIE0_RX4_P: length 10.5
  TOP w0.165: P1.B60 63.55,11.83 v2(63.59,11.79)
  BOTTOM w0.165: P2.A49 63.35,5.17 62.99,5.53 62.99,8.13 63.32,8.46 63.32,11.51 v2(63.59,11.79)
PCIE0_RX5_N: length 10.5
  TOP w0.165: P1.B66 58.75,11.79 v2(58.75,11.79)
  BOTTOM w0.165: P2.A54 58.35,5.17 58.71,5.53 58.71,9.48 59.05,9.82 59.05,11.48 v2(58.75,11.79)
PCIE0_RX5_P: length 10.5
  TOP w0.165: v2(59.59,11.79) 59.55,11.83 P1.B65
  BOTTOM w0.165: P2.A53 59.35,5.16 58.99,5.53 58.99,9.37 59.33,9.71 59.33,11.52 v2(59.59,11.79)
PCIE0_RX6_N: length 10.5
  TOP w0.165: P1.B71 54.75,11.78 v2(54.73,11.76)
  BOTTOM w0.165: P2.A58 54.35,5.16 54.71,5.53 54.71,8.42 55.01,8.73 55.01,11.48 v2(54.73,11.76)
PCIE0_RX6_P: length 10.5
  TOP w0.165: P1.B70 55.55,11.79 v2(55.58,11.76)
  BOTTOM w0.165: P2.A57 55.35,5.17 54.99,5.53 54.99,8.31 55.29,8.61 55.29,11.47 v2(55.58,11.76)
PCIE0_RX7_N: length 10.5
  TOP w0.165: P1.B76 50.75,11.79 v2(50.74,11.79)
  BOTTOM w0.165: v2(50.74,11.79) 51.04,11.49 51.04,8.97 50.71,8.64 50.71,5.53 50.35,5.16 P2.A62
PCIE0_RX7_P: length 10.5
  TOP w0.165: P1.B75 51.55,11.83 v2(51.59,11.79)
  BOTTOM w0.165: v2(51.59,11.79) 51.32,11.51 51.32,8.85 50.99,8.53 50.99,5.53 51.35,5.17 P2.A61
PCIE0_TX0_N: length 5.8
  TOP w0.165: P1.A19 96.35,7.54 96.61,7.27 96.61,5.85 96.71,5.75 96.71,5.53 96.35,5.16 P2.B16
PCIE0_TX0_P: length 5.8
  TOP w0.165: P1.A18 97.15,7.54 96.89,7.28 96.89,5.96 96.99,5.87 96.99,5.53 97.35,5.17 P2.B15
PCIE0_TX1_N: length 5.8
  TOP w0.165: P2.B20 92.35,5.16 92.71,5.53 92.71,5.97 92.61,6.06 92.61,7.27 92.35,7.54 P1.A24
PCIE0_TX1_P: length 5.8
  TOP w0.165: P1.A23 93.15,7.54 92.89,7.28 92.89,6.18 92.99,6.08 92.99,5.53 93.35,5.17 P2.B19
PCIE0_TX2_N: length 5.8
  TOP w0.165: P2.B24 88.35,5.16 88.71,5.53 88.71,5.99 88.61,6.09 88.61,7.28 88.35,7.54 P1.A29
PCIE0_TX2_P: length 5.8
  TOP w0.165: P2.B23 89.35,5.17 88.99,5.53 88.99,6.11 88.89,6.21 88.89,7.28 89.15,7.54 P1.A28
PCIE0_TX3_N: length 5.8
  TOP w0.165: P1.A34 84.35,7.54 84.61,7.27 84.61,6.22 84.71,6.12 84.71,5.53 84.35,5.16 P2.B28
PCIE0_TX3_P: length 5.8
  TOP w0.165: P1.A33 85.15,7.54 84.89,7.28 84.89,6.33 84.99,6.24 84.99,5.53 85.35,5.17 P2.B27
PCIE0_TX4_N: length 5.8
  TOP w0.165: P1.A64 60.35,7.62 60.66,7.32 60.66,5.47 60.35,5.16 P2.B52
PCIE0_TX4_P: length 5.8
  TOP w0.165: P2.B51 61.35,5.17 60.93,5.58 60.93,7.32 61.15,7.54 P1.A63
PCIE0_TX5_N: length 5.8
  TOP w0.165: P1.A69 56.35,7.54 56.61,7.28 56.61,6.09 56.71,5.99 56.71,5.53 56.35,5.16 P2.B56
PCIE0_TX5_P: length 5.8
  TOP w0.165: P2.B55 57.35,5.17 56.99,5.53 56.99,6.11 56.89,6.21 56.89,7.28 57.15,7.54 P1.A68
PCIE0_TX6_N: length 5.8
  TOP w0.165: P1.A74 52.35,7.54 52.61,7.27 52.61,5.96 52.71,5.86 52.71,5.53 52.35,5.16 P2.B60
PCIE0_TX6_P: length 5.8
  TOP w0.165: P2.B59 53.35,5.17 52.99,5.53 52.99,5.98 52.89,6.07 52.89,7.28 53.15,7.54 P1.A73
PCIE0_TX7_N: length 5.8
  TOP w0.165: P2.B64 48.35,5.16 48.71,5.53 48.71,6.69 48.61,6.78 48.61,7.27 48.35,7.54 P1.A79
PCIE0_TX7_P: length 5.8
  TOP w0.165: P2.B63 49.35,5.17 48.99,5.53 48.99,6.8 48.89,6.9 48.89,7.28 49.15,7.54 P1.A78
PCIE1_REFCLK_N: length 5.8
  TOP w0.165: P1.A44 76.35,7.54 76.61,7.27 76.61,5.99 76.71,5.89 76.71,5.53 76.35,5.16 P2.B36
PCIE1_REFCLK_P: length 5.8
  TOP w0.165: P2.B35 77.35,5.17 76.99,5.53 76.99,6.01 76.89,6.1 76.89,7.28 77.15,7.54 P1.A43
PCIE1_RST_N: length 5.6
  TOP w0.203: P2.B39 73.15,3.4 P1.A48
PCIE1_RX0_N: length 10.5
  TOP w0.165: v2(46.76,11.79) 46.75,11.79 P1.B81
  BOTTOM w0.165: v2(46.76,11.79) 47.06,11.49 47.06,8.87 46.71,8.53 46.71,5.53 46.35,5.16 P2.A66
PCIE1_RX0_P: length 10.5
  TOP w0.165: v2(47.6,11.79) 47.55,11.84 P1.B80
  BOTTOM w0.165: P2.A65 47.35,5.17 46.99,5.53 46.99,8.41 47.33,8.76 47.33,11.52 v2(47.6,11.79)
PCIE1_RX1_N: length 10.5
  TOP w0.165: P1.B86 42.75,11.79 v2(42.74,11.79)
  BOTTOM w0.165: P2.A70 42.35,5.16 42.65,5.46 42.65,9.31 43.1,9.77 43.1,11.43 v2(42.74,11.79)
PCIE1_RX1_P: length 10.6
  TOP w0.165: P1.B85 43.55,11.83 v2(43.59,11.79)
  BOTTOM w0.165: v2(43.59,11.79) 43.38,11.57 43.38,9.65 42.93,9.2 42.93,5.59 43.35,5.17 P2.A69
PCIE1_RX2_N: length 11.4
  TOP w0.165: v2(38.73,11.79) 38.75,11.8 P1.B91
  BOTTOM w0.165: v2(38.73,11.79) 39.01,11.51 39.01,11.15 37.64,9.78 37.64,6.84 38.71,5.77 38.71,5.53 38.35,5.16 P2.A74
PCIE1_RX2_P: length 11.4
  TOP w0.165: P1.B90 39.55,11.81 v2(39.58,11.79)
  BOTTOM w0.165: P2.A73 39.35,5.17 38.99,5.53 38.99,5.88 37.92,6.95 37.92,9.66 39.29,11.03 39.29,11.5 v2(39.58,11.79)
PCIE1_RX3_N: length 11.2
  TOP w0.165: P1.B95 35.55,11.81 v2(35.53,11.79)
  BOTTOM w0.165: v2(35.53,11.79) 35.81,11.51 35.81,11.13 34.24,9.55 34.24,6.3 34.71,5.83 34.71,5.53 34.35,5.16 P2.A78
PCIE1_RX3_P: length 11.2
  TOP w0.165: v2(36.38,11.79) 36.35,11.81 P1.B94
  BOTTOM w0.165: v2(36.38,11.79) 36.09,11.5 36.09,11.01 34.52,9.44 34.52,6.42 34.99,5.94 34.99,5.53 35.35,5.17 P2.A77
PCIE1_TX0_N: length 5.8
  TOP w0.165: P1.A84 44.35,7.54 44.61,7.27 44.61,6.19 44.71,6.09 44.71,5.53 44.35,5.16 P2.B68
PCIE1_TX0_P: length 5.8
  TOP w0.165: P1.A83 45.15,7.54 44.89,7.28 44.89,6.3 44.99,6.21 44.99,5.53 45.35,5.17 P2.B67
PCIE1_TX1_N: length 5.8
  TOP w0.165: P1.A89 40.35,7.54 40.61,7.28 40.61,6.79 40.71,6.69 40.71,5.53 40.35,5.16 P2.B72
PCIE1_TX1_P: length 5.8
  TOP w0.165: P2.B71 41.35,5.17 40.99,5.53 40.99,6.81 40.89,6.91 40.89,7.28 41.15,7.54 P1.A88
PCIE1_TX2_N: length 6.1
  TOP w0.165: P2.B76 36.35,5.16 36.71,5.53 36.71,6.03 37.41,6.73 37.41,7.28 37.15,7.54 P1.A93
PCIE1_TX2_P: length 6.1
  TOP w0.165: P1.A92 37.95,7.54 37.69,7.28 37.69,6.61 36.99,5.91 36.99,5.53 37.35,5.17 P2.B75
PCIE1_TX3_N: length 6.6
  TOP w0.165: P2.B80 32.35,5.17 32.71,5.53 32.71,5.9 33.72,6.91 34.01,6.91 34.21,7.11 34.21,7.28 33.95,7.54 P1.A97
PCIE1_TX3_P: length 6.6
  TOP w0.165: P1.A96 34.75,7.54 34.49,7.28 34.49,7 34.13,6.63 33.84,6.63 32.99,5.79 32.99,5.53 33.35,5.16 P2.B79
PCIE2_REFCLK_N: length 10.5
  TOP w0.165: P1.B46 74.75,11.71 v2(74.75,11.71)
  BOTTOM w0.165: P2.A38 74.35,5.16 74.71,5.53 74.71,8.94 75.04,9.28 75.04,11.41 v2(74.75,11.71)
PCIE2_REFCLK_P: length 10.5
  TOP w0.165: v2(75.59,11.71) 75.55,11.75 P1.B45
  BOTTOM w0.165: v2(75.59,11.71) 75.32,11.44 75.32,9.16 74.99,8.83 74.99,5.53 75.35,5.17 P2.A37
PCIE2_RST_N: length 5.5
  TOP w0.203: P1.A49 P2.B40
PRSNT_N: length 12.4
  TOP w0.203: v2(110.77,11.58) 110.75,11.6 P1.B1
  BOTTOM w0.203: P2.A1 113.35,5.27 114.73,6.65 114.73,7.72 113.35,9.1 110.87,11.58 v2(110.77,11.58)
PWR_BTN_N: length 6.3
  TOP w0.203: P2.B8 106.35,5.08 105.56,5.87 105.56,6.07 104.35,7.28 P1.A9
RFU: length 10.5
  TOP w0.203: P1.B50 71.55,10.99 v2(71.52,10.96)
  BOTTOM w0.203: P2.A41 71.35,5.28 70.99,5.64 70.99,10.43 v2(71.52,10.96)
SATA0_RX_N: length 10.5
  TOP w0.152: P1.B41 78.75,11.77 v2(78.71,11.73)
  BOTTOM w0.152: v2(78.71,11.73) 79.03,11.42 79.03,9.22 78.67,8.87 78.67,5.48 78.35,5.16 P2.A34
SATA0_RX_P: length 10.5
  TOP w0.152: v2(79.63,11.73) 79.55,11.82 P1.B40
  BOTTOM w0.152: P2.A33 79.35,5.16 79.03,5.48 79.03,8.72 79.38,9.07 79.38,11.48 v2(79.63,11.73)
SATA0_TX_N: length 5.8
  TOP w0.152: P2.B32 80.35,5.16 80.67,5.48 80.67,6.02 80.58,6.12 80.58,7.31 80.35,7.54 P1.A39
SATA0_TX_P: length 5.8
  TOP w0.152: P1.A38 81.15,7.54 80.93,7.32 80.93,6.26 81.03,6.17 81.03,5.48 81.35,5.16 P2.B31
SVR_ID0: length 11.5
  TOP w0.203: v2(105.89,10.69) 105.89,13.22 P1.B7
  BOTTOM w0.203: v2(105.89,10.69) 105.89,10.49 107.14,9.25 107.14,7.57 109.35,5.36 P2.A5
SVR_ID1: length 11.4
  TOP w0.203: P1.B8 v2(105.15,11.69)
  BOTTOM w0.203: v2(105.15,11.69) 105.15,10.55 106.65,9.04 106.65,7.37 108.35,5.67 P2.A6
SVR_ID2: length 11.2
  TOP w0.203: P1.B11 102.75,10.96 102.74,10.95 v2(102.74,10.81)
  BOTTOM w0.203: P2.A9 105.35,5.15 104.97,5.53 104.97,8.44 102.75,10.66 102.75,10.8 v2(102.74,10.81)
SVR_ID3: length 11.1
  TOP w0.203: P1.B12 101.95,11.8 v2(101.95,11.8)
  BOTTOM w0.203: P2.A10 104.35,8.22 101.95,10.62 v2(101.95,11.8)
SYS_RST_N: length 6.8
  TOP w0.203: P2.B11 103.35,6 102.19,7.15 101.56,7.15 101.15,7.56 P1.A13
USB_DN: length 6.7
  TOP w0.14: P1.A11 102.75,7.54 103.02,7.27 103.02,7.02 103.91,6.13 104.33,6.13 104.72,5.74 104.72,5.53 104.35,5.16 P2.B10
USB_DP: length 6.7
  TOP w0.14: P2.B9 105.35,5.16 104.98,5.53 104.98,5.84 104.43,6.39 104.02,6.39 103.28,7.13 103.28,7.27 103.55,7.54 P1.A10

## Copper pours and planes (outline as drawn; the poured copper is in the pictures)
12V_1 on TOP: 107.34,14.35 110.21,14.35 110.28,14.27 110.28,11.4 110.71,10.97 112.34,10.97 114.24,9.07 114.24,5.26 110.71,5.26 110.71,5.87 110.54,6.05 109.17,6.05 108.84,6.38 108.07,6.38 107.34,7.1
12V_1 on BOTTOM: 110.28,12.06 110.28,11.33 110.64,10.97 110.97,10.97 114.12,7.83 114.12,7.82 114.12,6.58 112.92,5.38 112.92,4.19 110.71,4.19 110.71,5.03 110.38,5.36 109.83,5.36 107.48,7.71 107.48,10.88 107.34,11.02 107.34,12.06
12V_2 on TOP: 27.66,13.74 33.42,13.74 33.42,11.23 33.12,10.92 32,10.92 31.8,10.72 31.8,6.86 31,6.06 30.99,6.07 27.66,6.07
12V_2 on BOTTOM: 29.74,4.19 29.74,6.38 27.66,6.38 27.66,13.74 33.42,13.74 33.42,11.23 33.12,10.92 32,10.92 31.8,10.72 31.8,4.42 31.57,4.19
GND on TOP (solid shape): outline of 222 points within 4.95,4.95 11.05,11.05
GND on TOP (solid shape): outline of 222 points within 124.45,4.95 130.55,11.05
GND on BOTTOM (solid shape): outline of 222 points within 4.95,4.95 11.05,11.05
GND on BOTTOM (solid shape): outline of 222 points within 124.45,4.95 130.55,11.05
GND on BOTTOM: 100.18,10.77 100.18,8.44 99.83,8.09 99.83,6.71 103.33,6.71 103.4,6.77 103.4,7.78 101.01,10.16 101.01,10.77
GND on BOTTOM: 11.79,14.96 11.79,8.71 27.15,8.71 27.15,14.96
GND on L2_GND, L3_GND: 1.02,1.4 1.02,14.98 134.48,14.98 134.48,1.4 103.82,1.4 103.82,5.05 101.85,7.02 99.88,5.05 99.88,1.4

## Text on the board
Ref Des/Silkscreen Top: AESIHPCI
User.21: FIGURE | SIZE | 10.0 | 15.0 | 20.0 | 31.0 | 47.0 | 87.0 | 126.0 | DRILL CHART: TOP to BOTTOM | ALL UNITS ARE IN MILS | TOLERANCE | +3.0/-3.0 | +2.0/-2.0 | PLATED | NON-PLATED | QTY | 126 | 16 | 141 | 1 | 2
